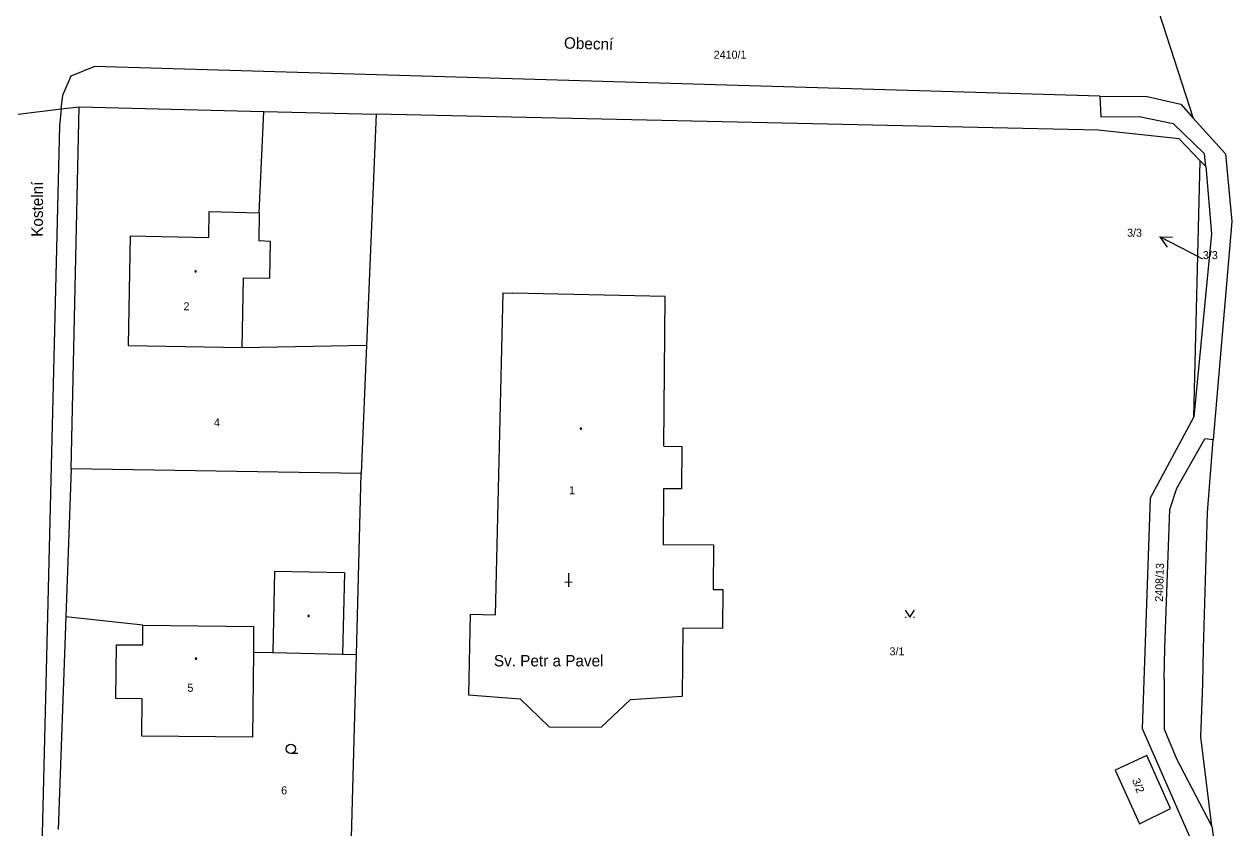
# Model space of a CAD drawing. Extents: x -454285 to -453563, y -1108687 to -1108249.
# Drawn here: x -453760.9 to -453655.3, y -1108546.8 to -1108476.5 of the extents above; entities that cross this region are included whole.
import ezdxf

# ---------------------------------------------------------------- set-up
doc = ezdxf.new("R2010")
doc.units = 0
for name, color, linetype in [('1', 7, 'Continuous'), ('13', 7, 'Continuous'), ('14', 7, 'Continuous'), ('15', 7, 'Continuous'), ('16', 7, 'Continuous'), ('2', 7, 'Continuous'), ('23', 7, 'Continuous'), ('25', 7, 'Continuous'), ('38', 7, 'Continuous')]:
    doc.layers.add(name, color=color, linetype=linetype)

# ---------------------------------------------------------------- blocks, each defined once
blk = doc.blocks.new('Z402')
for start, end in [(0, 180), (180, 0)]:
    blk.add_arc((0, 0), 0.15, start, end)
blk = doc.blocks.new('Z4090')
for p, q in [((0, 0), (0, 3)), ((-0.8, 2), (0.8, 2))]:
    blk.add_line(p, q)
blk = doc.blocks.new('Z3140')
for p, q in [((-1, 1.5), (0, 0)), ((-1, 0), (-0.8, 0)), ((0, 0), (1, 1.5)), ((0.8, 0), (1, 0))]:
    blk.add_line(p, q)
blk = doc.blocks.new('Z3040')
blk.add_line((1.5, 0), (0, 0))
blk.add_circle((0, 1), 1)
blk = doc.blocks.new('Z61')
for p, q in [((0, 3), (-0.5, 2)), ((0, 0), (0, 3)), ((0, 3), (0.5, 2))]:
    blk.add_line(p, q)

msp = doc.modelspace()

# ---------------------------------------------------------------- linework, layer by layer
at = {"layer": '1'}
for p, q in [((-453662.02, -1108474.34), (-453658.66, -1108484.7)), ((-453666.83, -1108482.8), (-453662.68, -1108482.81)), ((-453666.83, -1108482.8), (-453666.75, -1108484.6)), ((-453662.68, -1108482.81), (-453659.75, -1108483.48)), ((-453761.45, -1108484.37), (-453757.69, -1108483.91)), ((-453757.69, -1108483.91), (-453756.11, -1108483.73)), ((-453756.82, -1108515.41), (-453756.11, -1108483.73)), ((-453756.11, -1108483.73), (-453739.97, -1108484.13)), ((-453740.36, -1108492.99), (-453739.97, -1108484.13)), ((-453739.97, -1108484.13), (-453730.13, -1108484.37)), ((-453730.13, -1108484.37), (-453730.97, -1108504.57)), ((-453666.98, -1108485.75), (-453730.13, -1108484.37)), ((-453659.75, -1108483.48), (-453658.66, -1108484.7)), ((-453666.75, -1108484.6), (-453663.38, -1108484.56)), ((-453663.38, -1108484.56), (-453660.42, -1108485.18)), ((-453660.42, -1108485.18), (-453657.67, -1108487.84)), ((-453658.66, -1108484.7), (-453655.85, -1108487.84)), ((-453659.9, -1108486.52), (-453666.98, -1108485.75)), ((-453659.9, -1108486.52), (-453658.05, -1108488.44)), ((-453658.6, -1108510.85), (-453658.05, -1108488.44)), ((-453658.05, -1108488.44), (-453657.57, -1108488.93)), ((-453657.57, -1108488.93), (-453657.67, -1108487.84)), ((-453655.85, -1108487.84), (-453655.29, -1108493.75)), ((-453657.57, -1108488.93), (-453657.07, -1108494.85)), ((-453744.78, -1108495.15), (-453744.74, -1108492.88)), ((-453744.74, -1108492.88), (-453740.36, -1108492.99)), ((-453655.29, -1108493.75), (-453656.91, -1108512.87)), ((-453657.07, -1108494.85), (-453658.6, -1108510.85)), ((-453751.66, -1108495.02), (-453751.84, -1108504.6)), ((-453751.66, -1108495.02), (-453744.78, -1108495.15)), ((-453719.69, -1108528.18), (-453719.03, -1108500)), ((-453719.03, -1108500), (-453718.17, -1108500.02)), ((-453704.86, -1108500.33), (-453718.17, -1108500.02)), ((-453704.96, -1108513.43), (-453704.86, -1108500.33)), ((-453751.84, -1108504.6), (-453741.87, -1108504.79)), ((-453741.87, -1108504.79), (-453730.97, -1108504.57)), ((-453730.97, -1108504.57), (-453731.44, -1108515.81)), ((-453658.6, -1108510.85), (-453662.44, -1108517.96)), ((-453660.09, -1108517.11), (-453657.64, -1108512.77)), ((-453656.91, -1108512.87), (-453657.64, -1108512.77)), ((-453704.96, -1108513.43), (-453703.39, -1108513.44)), ((-453703.39, -1108513.44), (-453703.42, -1108517.17)), ((-453756.82, -1108515.41), (-453757.29, -1108528.36)), ((-453731.44, -1108515.81), (-453756.82, -1108515.41)), ((-453731.87, -1108531.66), (-453731.44, -1108515.81)), ((-453660.72, -1108518.97), (-453660.09, -1108517.11)), ((-453704.99, -1108517.16), (-453705.03, -1108522.04)), ((-453703.42, -1108517.17), (-453704.99, -1108517.16)), ((-453662.44, -1108517.96), (-453663.12, -1108538.12)), ((-453661.14, -1108531.06), (-453660.72, -1108518.97)), ((-453705.03, -1108522.04), (-453700.63, -1108522.07)), ((-453700.63, -1108522.07), (-453700.66, -1108525.97)), ((-453700.66, -1108525.97), (-453699.81, -1108525.98)), ((-453699.81, -1108525.98), (-453699.83, -1108529.38)), ((-453757.29, -1108528.36), (-453757.97, -1108546.98)), ((-453750.55, -1108529.09), (-453757.29, -1108528.36)), ((-453721.91, -1108528.13), (-453722.07, -1108535.18)), ((-453721.91, -1108528.13), (-453719.69, -1108528.18)), ((-453750.56, -1108530.82), (-453750.55, -1108529.09)), ((-453703.31, -1108529.35), (-453703.36, -1108535.29)), ((-453699.83, -1108529.38), (-453703.31, -1108529.35)), ((-453752.9, -1108535.51), (-453752.85, -1108530.8)), ((-453752.85, -1108530.8), (-453750.56, -1108530.82)), ((-453740.88, -1108531.45), (-453740.95, -1108538.9)), ((-453740.88, -1108531.45), (-453739.18, -1108531.49)), ((-453739.18, -1108531.49), (-453733.09, -1108531.63)), ((-453733.09, -1108531.63), (-453731.87, -1108531.66)), ((-453732.31, -1108547.66), (-453731.87, -1108531.66)), ((-453661.22, -1108533.83), (-453661.14, -1108531.06)), ((-453661.22, -1108533.83), (-453661.22, -1108538.19)), ((-453750.62, -1108535.53), (-453752.9, -1108535.51)), ((-453750.65, -1108538.81), (-453750.62, -1108535.53)), ((-453722.07, -1108535.18), (-453717.54, -1108535.55)), ((-453717.54, -1108535.55), (-453715, -1108537.99)), ((-453710.47, -1108538.02), (-453707.89, -1108535.61)), ((-453707.89, -1108535.61), (-453703.36, -1108535.29)), ((-453715, -1108537.99), (-453710.47, -1108538.02)), ((-453663.12, -1108538.12), (-453658.57, -1108548.53)), ((-453661.22, -1108538.19), (-453660.16, -1108540.71)), ((-453740.95, -1108538.9), (-453750.65, -1108538.81)), ((-453662.73, -1108540.5), (-453665.5, -1108541.79)), ((-453660.66, -1108545.13), (-453662.73, -1108540.5)), ((-453657.03, -1108546.68), (-453660.16, -1108540.71)), ((-453665.5, -1108541.79), (-453663.36, -1108546.49)), ((-453663.36, -1108546.49), (-453660.66, -1108545.13)), ((-453657.03, -1108546.68), (-453656.78, -1108548.59))]:
    msp.add_line(p, q, dxfattribs=at)
at = {"layer": '13'}
msp.add_line((-453657.82, -1108497.05), (-453658.93, -1108496.48), dxfattribs=at)
at = {"layer": '2'}
for p, q in [((-453757.54, -1108482.71), (-453756.83, -1108481.02)), ((-453756.83, -1108481.02), (-453754.8, -1108480.2)), ((-453666.83, -1108482.8), (-453754.8, -1108480.2)), ((-453757.69, -1108483.91), (-453757.54, -1108482.71)), ((-453757.69, -1108483.91), (-453757.83, -1108485.39)), ((-453757.83, -1108485.39), (-453759.39, -1108548.56)), ((-453740.36, -1108492.99), (-453740.41, -1108495.44)), ((-453739.39, -1108495.5), (-453740.41, -1108495.44)), ((-453739.45, -1108498.72), (-453739.39, -1108495.5)), ((-453741.87, -1108504.79), (-453741.75, -1108498.68)), ((-453741.75, -1108498.68), (-453739.45, -1108498.72)), ((-453657.43, -1108519.24), (-453656.91, -1108512.87)), ((-453657.76, -1108531.12), (-453657.43, -1108519.24)), ((-453739.02, -1108524.38), (-453739.18, -1108531.49)), ((-453732.92, -1108524.5), (-453739.02, -1108524.38)), ((-453732.92, -1108524.5), (-453733.09, -1108531.63)), ((-453750.55, -1108529.09), (-453740.86, -1108529.22)), ((-453740.86, -1108529.22), (-453740.88, -1108531.45)), ((-453657.83, -1108534.23), (-453657.76, -1108531.12)), ((-453658, -1108538.87), (-453657.83, -1108534.23)), ((-453657.03, -1108546.68), (-453658, -1108538.87))]:
    msp.add_line(p, q, dxfattribs=at)

# ---------------------------------------------------------------- block references
at = {"layer": '16', "rotation": 62.561899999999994}
msp.add_blockref('Z61', (-453658.93, -1108496.48), dxfattribs=at)
at = {"layer": '23', "xscale": 0.39999999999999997, "yscale": 0.40000000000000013, "rotation": 179.2169}
msp.add_blockref('Z4090', (-453713.31, -1108524.54), dxfattribs=at)
at = {"layer": '23', "xscale": 0.4, "yscale": 0.4000000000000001}
for name, p in [('Z3140', (-453683.45, -1108528.39)), ('Z3040', (-453737.6, -1108540.31))]:
    msp.add_blockref(name, p, dxfattribs=at)
at = {"layer": '25', "xscale": 0.4, "yscale": 0.4000000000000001}
for p in [(-453745.94, -1108498.13), (-453712.23, -1108511.88), (-453736.05, -1108528.28), (-453745.9, -1108532.02)]:
    msp.add_blockref('Z402', p, dxfattribs=at)

# ---------------------------------------------------------------- texts
at = {"layer": '14'}
for s, p in [('3/3', (-453657.82, -1108497.05)), ('4', (-453744.33, -1108511.7)), ('3/1', (-453685.23, -1108531.73)), ('6', (-453738.45, -1108543.9))]:
    msp.add_text(s, height=0.7, dxfattribs=at).set_placement(p)
for s, rotation, p in [('2408/13', 88.353, (-453661.32, -1108527.05)), ('3/2', 291.177, (-453664.03, -1108542.65))]:
    msp.add_text(s, height=0.7, rotation=rotation, dxfattribs=at).set_placement(p)
at = {"layer": '15'}
for s, p in [('2', (-453746.99, -1108501.53)), ('1', (-453713.26, -1108517.63)), ('5', (-453746.65, -1108534.92))]:
    msp.add_text(s, height=0.7, dxfattribs=at).set_placement(p)
at = {"layer": '16'}
msp.add_text('2410/1', height=0.7, rotation=0.1968, dxfattribs=at).set_placement((-453700.61, -1108479.51))
msp.add_text('3/3', height=0.7, dxfattribs=at).set_placement((-453664.45, -1108495.09))
at = {"layer": '38'}
for s, rotation, p in [('Obecní', 358.326, (-453713.72, -1108478.62)), ('Kostelní', 89.721, (-453759.3, -1108495.1))]:
    msp.add_text(s, height=1, rotation=rotation, dxfattribs=at).set_placement(p)
msp.add_text('Sv. Petr a Pavel', height=1, dxfattribs=at).set_placement((-453719.84, -1108532.7))

doc.saveas('drawing.dxf')
